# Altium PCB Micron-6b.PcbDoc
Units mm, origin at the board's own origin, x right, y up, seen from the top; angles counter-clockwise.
Board outline 45.08 x 23 mm, 2 copper layers (Top Layer, Bottom Layer), stack 1.021 mm thick; 39 components, 25 nets, 135 pads, 41 vias.
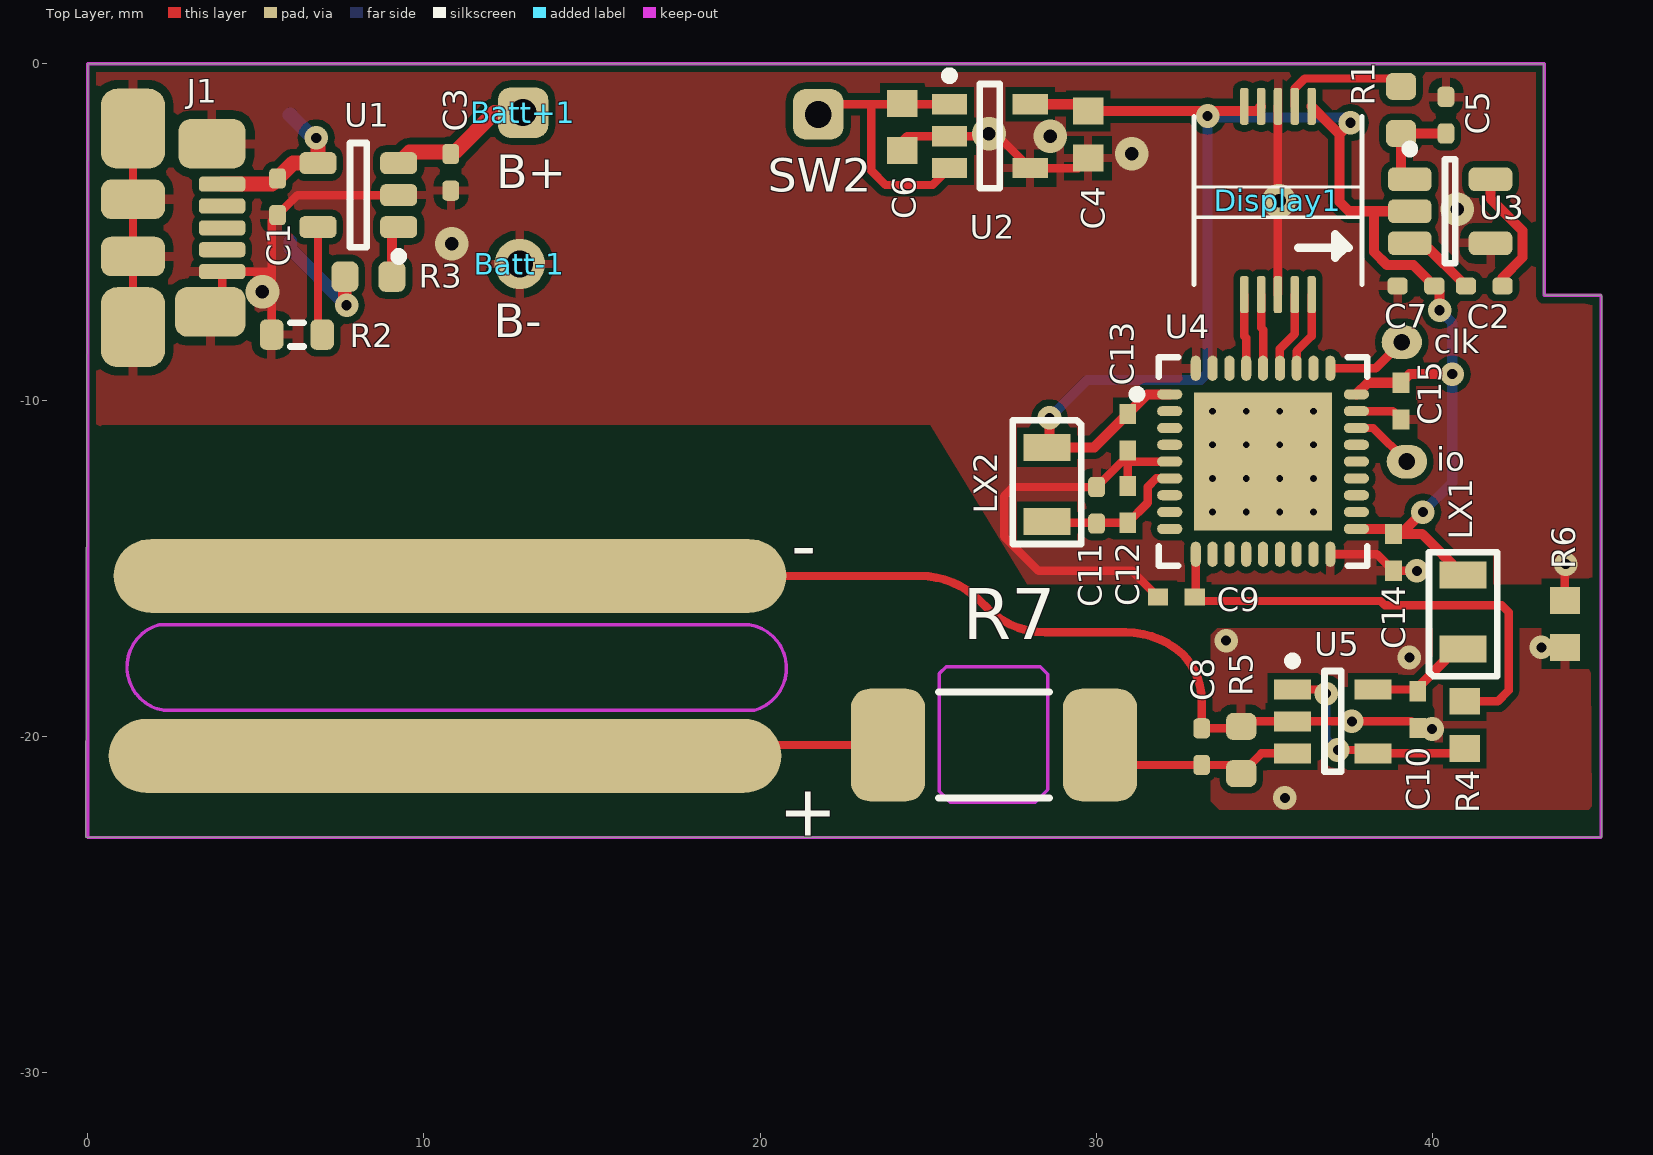
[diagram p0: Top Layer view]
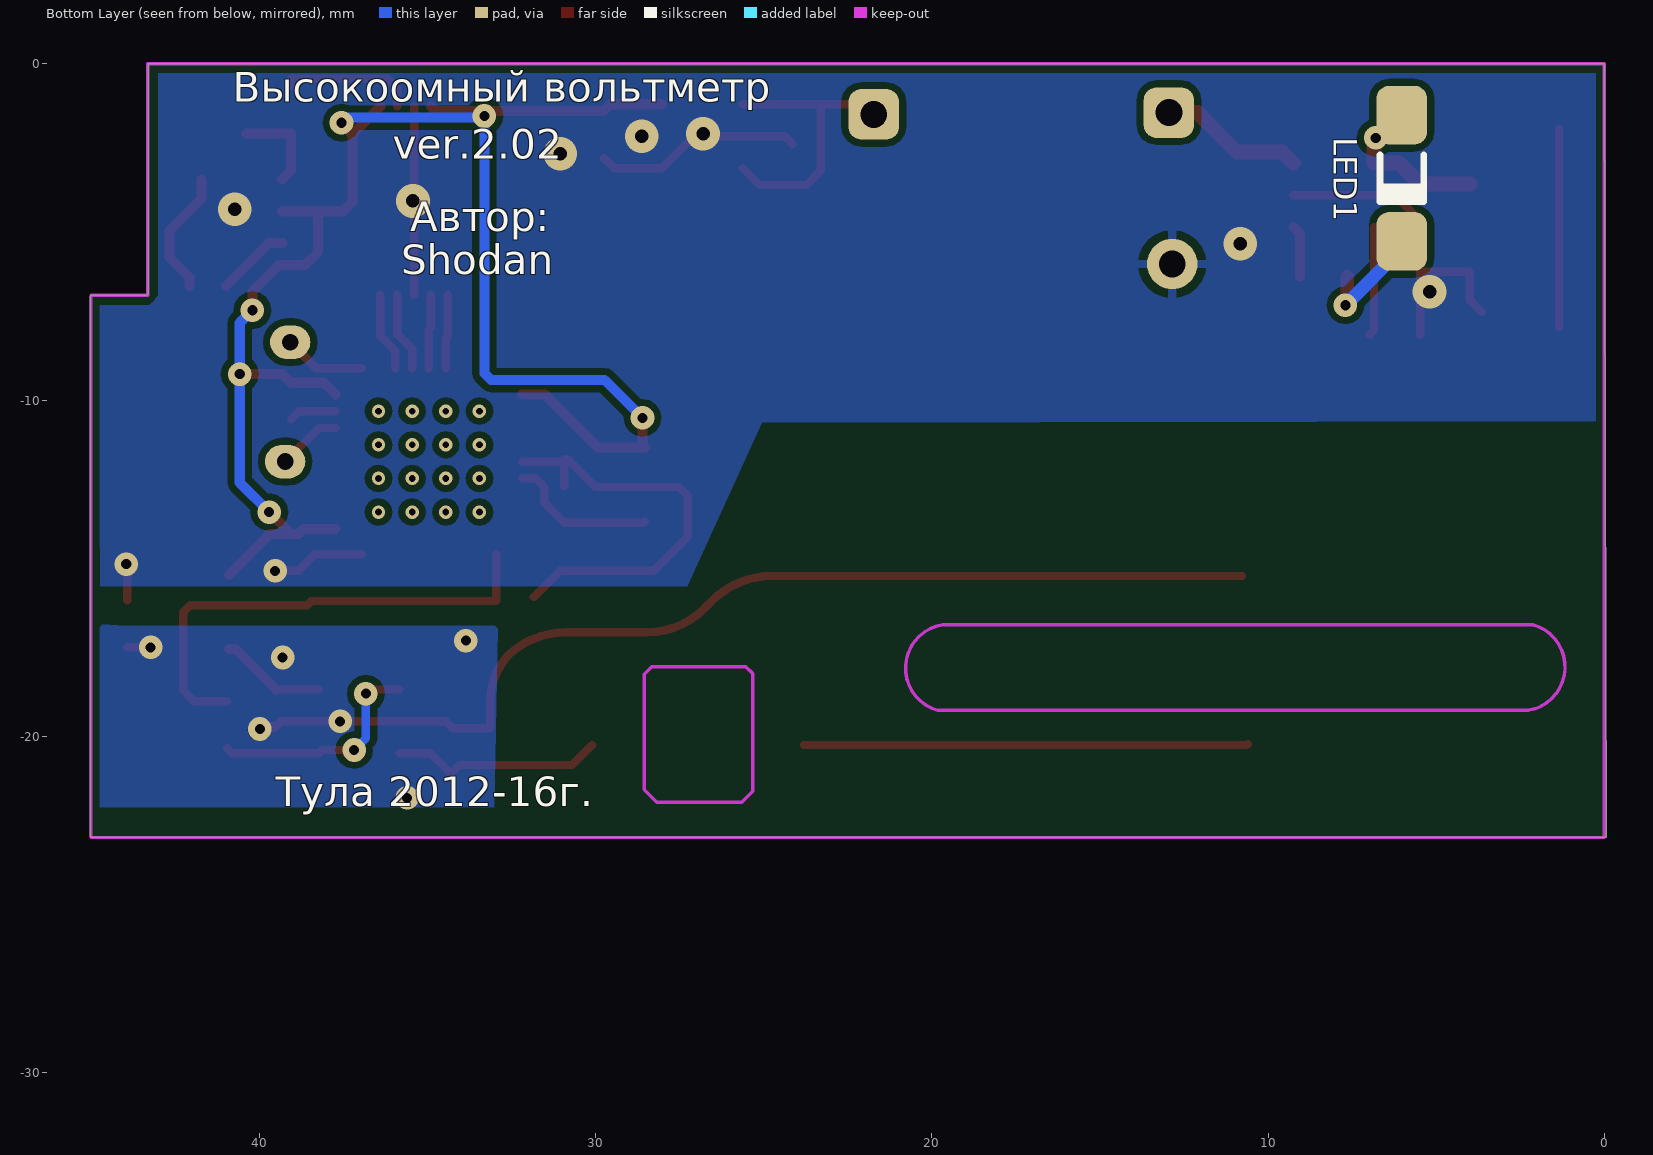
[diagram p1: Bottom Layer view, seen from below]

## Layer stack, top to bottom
Top Solder: solder mask 0.0102, Solder Resist, Dk 3.5
Top Layer: signal copper 0.0356
Dielectric1: dielectric 0.95, FR-4, Dk 4.8
Bottom Layer: signal copper 0.0356
Bottom Solder: solder mask 0.0102, Solder Resist, Dk 3.5

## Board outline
0,0 43.3,0 43.3,-6.85 43.325,-6.875 45,-6.875 45.025,-6.9 45.025,-23 0.1,-23 -0.05,-23

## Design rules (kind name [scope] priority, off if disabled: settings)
AssemblyTestPointUsage SilkToBoardRegionClearance_1 [All] p2:
Clearance Clearance_NetD2_1 [InNet('NetD2_1')] p1: gap=0.2
Clearance Clearance_NetC1_2 [InNet('NetC1_2')] p2: gap=0.2
Clearance Clearance_NetC1_1 [InNet('NetC1_1')] p3: gap=0.2
Clearance Clearance_400V [InNet('+400V')] p4: gap=0.8
Clearance Clearance_poly [InPolygon] p5: gap=0.2
Clearance [All] p6: gap=0.152
MatchedLengths DiffPair_DIFF100MatchedLengths [InDifferentialPairClass('DIFF100')] p1: tolerance=0.152 checknetsindiffpair=TRUE checkdiffpairvsdiffpair=FALSE checkxsignals=FALSE checkothers=FALSE
MinimumAnnularRing [All] p1: minimumring=0.152
MinimumSolderMaskSliver SilkscreenOverComponentPads_1 [All] p1: minsoldermaskwidth=0.254
MinimumSolderMaskSliver SilkToSolderMaskClearance [IsPad] p2: minsoldermaskwidth=0.254
MinimumSolderMaskSliver [All] p3: minsoldermaskwidth=0.254
MinimumSolderMaskSliver SilkscreenOverComponentPads_2 [All] p4: minsoldermaskwidth=0.254
PolygonConnect PolygonConnect_via [IsVia] p1: connectstyle=Direct reliefconductorwidth=0.254 reliefentries=4 polygonreliefangle="90 Angle" airgapwidth=0.254
PolygonConnect [All] p2: connectstyle=Relief reliefconductorwidth=0.254 reliefentries=4 polygonreliefangle="90 Angle" airgapwidth=0.254
RoutingVias [All] p1: holewidth=0.305 width=0.635 viastyle="Through Hole" minholewidth=0.305 minwidth=0.635 maxholewidth=0.711 maxwidth=1.27
ShortCircuit ShortCircuit_1 [All] p1: allowed=FALSE
ShortCircuit [All] p2: allowed=FALSE
SilkToBoardRegionClearance SilkToBoardRegionClearance_2 [All] p1:
SilkToBoardRegionClearance [All] p2:
SilkToSilkClearance [All] p1: silktosilkclearance=0.152
SilkToSolderMaskClearance SilkToSolderMaskClearance_1 [IsPad] p1: minsilkscreentomaskgap=0.254 clearancetoexposedcopper=TRUE
SilkToSolderMaskClearance SilkscreenOverComponentPads [IsPad] p2: minsilkscreentomaskgap=0.1 clearancetoexposedcopper=TRUE
SolderMaskExpansion [All] p1: expansion=0.102
Width [All] p1: maxlimit=2.54 minlimit=0.152 preferedwidth=0.254
25 further rules are at their usual default settings.

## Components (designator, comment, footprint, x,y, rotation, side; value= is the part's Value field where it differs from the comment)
+ "" "Sensor contact"#1 10.625,-20.575 r180 top (schematic designator HV+)
- "" "Sensor contact"#1 10.775,-15.225 r180 top (schematic designator HV-)
Batt+1 "" "SENSOR CONTACT"#1 12.575,-3.225 r90 top
Batt-1 "" "SENSOR CONTACT"#2 12.85,-5.95 r90 top
C1 "1uF" "0402 AVX"#1 5.65,-3.95 r180 top
C2 "1uF" "0402 AVX"#1 41.529,-6.604 r270 top
C3 "1uF" "0402 AVX"#1 10.8,-3.225 r180 top
C4 "1uF" 1608[0603]#1 29.75,-2.1 r90 top
C5 "1uF" "0402 AVX"#1 40.386,-1.524 r0 top
C6 "1uF" 1608[0603]#1 24.225,-1.875 r90 top
C7 "100nF" "0402 AVX"#1 39.497,-6.604 r90 top
C8 "100pF" "0402 AVX"#1 33.125,-20.3 r180 top
C9 "10nF" "0402 AVX"#2 32.375,-15.85 r270 top
C10 "100nF" "0402 AVX"#2 39.55,-19.2 r0 top
C11 "100nF" "0402 AVX"#1 30,-13.125 r180 top
C12 "100nF" "0402 AVX"#2 30.925,-13.1 r180 top
C13 "100nF" "0402 AVX"#2 30.925,-10.95 r0 top
C14 "100nF" "0402 AVX"#2 38.825,-14.525 r0 top
C15 "100nF" "0402 AVX"#2 39.05,-10.025 r0 top
clk "" "SENSOR CONTACT"#3 39.075,-8.275 r90 top
Display1 "Nokia 2760" DF23C-10DS-0.5V 32.893,-1.46 r90 top
io "" "SENSOR CONTACT"#3 39.225,-11.825 r90 top
J1 "Micro-USB" 47346-0001 4.75,-4.875 r270 top
LED1 "KPTD-3216SECK" KPTD-3216SECK 6.025,-3.4 r90 bottom
LX1 "Ferrite beard" Resistor 40.9,-16.3 r270 top
LX2 "Ferrite beard" Resistor 28.525,-12.5 r90 top
R1 "1R" 1608[0603]#2 39.052,-1.369 r270 top
R2 "10K" J1-0603 6.225,-8.05 r0 top
R3 "470R" 1608[0603]#2 8.35,-6.325 r180 top
R4 "10k" 1608[0603]#1 40.95,-19.65 r270 top
R5 "2.7M" 1608[0603]#2 34.3,-20.4 r90 top
R6 "0R" 1608[0603]#1 43.925,-16.65 r90 top
R7 "5G" HVF2512T5007FE 30.1,-21.925 r0 top
SW2 "" "Sensor contact"#2 21.725,-1.5 r90 top
U1 "MCP73831T-2ACI/OT" SOT-23-OT5_N 8.05,-3.9 r180 top
U2 "TPS78330DDCR" TI-DDC5_N 26.825,-2.15 r0 top
U3 "TPS60400DBV" SOT-23-OT5_M 40.513,-4.381 r0 top
U4 "STM32F103T8U6" VFQN36_V 34.95,-11.825 r0 top
U5 "AD8541ARTZ" ADI-RJ-5_N 37.025,-19.55 r0 top

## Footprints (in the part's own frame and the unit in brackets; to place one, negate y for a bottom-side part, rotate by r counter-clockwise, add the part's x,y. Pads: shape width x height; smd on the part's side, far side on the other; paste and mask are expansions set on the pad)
"0402 AVX"#1 [mm]
  rrect50% 0.5x0.6 smd: 1(0,0.545) 2(0,-0.545)
  body extent -0.25,-0.48 0.25,0.52, height 0.56
"0402 AVX"#2 [mm]
  rect 0.5x0.6 smd: 1(0,0.545) 2(0,-0.545)
  body extent -0.26,-0.5 0.26,0.5, height 0.36
1608[0603]#1 [mm] "Chip Capacitor, Body 1.6x0.8mm, IPC High Density"
  rect 0.8x0.9 smd: 1(-0.7,0) 2(0.7,0)
  body extent -0.87,-0.48 0.87,0.48, height 1.3
1608[0603]#2 [mm] "Chip Capacitor, Body 1.6x0.8mm, IPC High Density"
  rrect50% 0.8x0.9 smd: 1(-0.7,0) 2(0.7,0)
  body extent -0.87,-0.48 0.87,0.48, height 1.3
47346-0001 [mm] "Molex Mico-USB"
  rrect50% 0.45x1.38 smd: 1(-1.3,-0.75) 2(-0.65,-0.75) 3(0,-0.75) 4(0.65,-0.75) 5(1.3,-0.75)
  rrect50% 1.475x2 smd: MH1(-2.5,-1.05)
  rrect50% 1.475x2.1 smd: MH2(2.5,-1.1)
  rrect50% 2.375x1.9 smd: MH3(-2.95,-3.4) MH4(2.95,-3.4)
  rrect50% 1.175x1.9 smd: MH3(-0.85,-3.4) MH4(0.85,-3.4)
  body extent -3.95,-5.52 4.03,-0.09, height 2.77
ADI-RJ-5_N [mm] "SOT-23, 5-Leads, Body 2.9x1.6mm, Pitch 0.95mm, IPC Medium Density"
  rect 1.1x0.6 smd: 1(-1.2,0.95) 2(-1.2,0) 3(-1.2,-0.95) 4(1.2,-0.95) 5(1.2,0.95)
  silkscreen extent -1.32,-1.5 0.25,1.92, body extent -0.85,-1.5 0.85,1.5, height 1.45
DF23C-10DS-0.5V [mm]
  rrect50% 1.1x0.25 smd: 1(-5.4,-1.5) 2(-5.4,-2) 3(-5.4,-2.5) 4(-5.4,-3) 5(-5.4,-3.5) 6(0.2,-3.5) 7(0.2,-3) 8(0.2,-2.5) 9(0.2,-2) 10(0.2,-1.5)
  silkscreen extent -5.1,-5 -0.1,0, body extent -5.1,-5 -0.1,0, height 1.4
HVF2512T5007FE [mm] "Chip Resistor, 2-Leads, Body 7,31x3,20mm, IPC Low Density"
  rrect50% 2.2x3.35 smd: 1(-6.3,1.675) 2(0,1.675)
  silkscreen extent -4.8,0.1 -1.5,3.25, body extent -6.8,0.08 0.51,3.27, height 0.82
J1-0603 [mm] "Chip Resistor, Body 1.6x0.8mm, IPC High Density"
  rrect50% 0.7x0.9 smd: 1(-0.75,0) 2(0.75,0)
  silkscreen extent -0.2,-0.35 0.2,0.35, body extent -0.85,-0.48 0.85,0.48, height 0.9
KPTD-3216SECK [mm] "Chip Capacitor, 2-Leads, Body 3,2x1,6mm, IPC Medium Density"
  rrect50% 1.75x1.5 smd: 1(-1.875,0) 2(1.875,0)
  silkscreen extent -0.7,-0.65 0.7,0.65, body extent -1.6,-0.8 1.6,0.8, height 1.8
Resistor [mm]
  rect 0.8x1.4 smd: 1(-1.1,0) 2(1.1,0)
  silkscreen extent -1.78,-1.02 1.91,1.02, body extent -1.1,-0.7 1.2,0.7, height 1
"Sensor contact"#1 [mm]
  oval 20x2.2 smd: 1(0,0)
"Sensor contact"#2 [mm]
  rrect50% 1.5x1.5 hole 0.8: 1(0,0)
"SENSOR CONTACT"#1 [mm]
  rrect50% 1.5x1.5 hole 0.8: 1(1.775,-0.375)
"SENSOR CONTACT"#2 [mm]
  round 1.5 hole 0.8: 1(0,0)
"SENSOR CONTACT"#3 [mm]
  oval 1x1.2 hole 0.5: 1(0,0)
SOT-23-OT5_M [mm] "SOT23, 5-Leads, Body 2.9x1.6mm, Pitch 0.95mm, Lead Span 2.7mm, IPC Low Density"
  rrect50% 1.3x0.7 smd: 1(-1.2,0.95) 2(-1.2,0) 3(-1.2,-0.95) 4(1.2,-0.95) 5(1.2,0.95)
  silkscreen extent -1.32,-1.55 0.15,1.97, body extent -0.9,-1.55 0.9,1.55, height 1.45
SOT-23-OT5_N [mm] "SOT23, 5-Leads, Body 2.9x1.6mm, Pitch 0.95mm, Lead Span 2.7mm, IPC Medium Density"
  rrect50% 1.1x0.65 smd: 1(-1.2,0.95) 2(-1.2,0) 3(-1.2,-0.95) 4(1.2,-0.95) 5(1.2,0.95)
  silkscreen extent -1.33,-1.55 0.25,1.95, body extent -0.9,-1.55 0.9,1.55, height 1.45
TI-DDC5_N [mm] "SOT23, 5-Leads, Body 2.9x1.6mm, Pitch 0.95mm, IPC Medium Density"
  rect 1.05x0.6 smd: 1(-1.2,0.95) 2(-1.2,0) 3(-1.2,-0.95) 4(1.2,-0.95) 5(1.2,0.95)
  silkscreen extent -1.32,-1.55 0.3,1.92, body extent -0.87,-1.52 0.87,1.53, height 1.1
VFQN36_V [mm] "QFN, 36-Leads, Body 6x6mm, Pitch 0.5mm, ST Recommended"
  oval 0.75x0.3 smd: 1(-2.775,2) 2(-2.775,1.5) 3(-2.775,1) 4(-2.775,0.5) 5(-2.775,0) 6(-2.775,-0.5) 7(-2.775,-1) 8(-2.775,-1.5) 9(-2.775,-2) 19(2.775,-2) 20(2.775,-1.5) 21(2.775,-1) 22(2.775,-0.5) 23(2.775,0) 24(2.775,0.5) 25(2.775,1) 26(2.775,1.5) 27(2.775,2)
  oval 0.3x0.75 smd: 10(-2,-2.755) 11(-1.5,-2.755) 12(-1,-2.755) 13(-0.5,-2.755) 14(0,-2.755) 15(0.5,-2.755) 16(1,-2.755) 17(1.5,-2.755) 18(2,-2.755) 28(2,2.775) 29(1.5,2.775) 30(1,2.775) 31(0.5,2.775) 32(0,2.775) 33(-0.5,2.775) 34(-1,2.775) 35(-1.5,2.775) 36(-2,2.775)
  rect 4.1x4.1 smd: 37(0,0)
  silkscreen extent -3.87,-3.1 3.1,3.1, body extent -3.05,-3.05 3.05,3.05, height 1

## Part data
+ - Batt+1 Batt-1 clk io SW2: library part Plug, "Plug"
C1 C2 C3 C5 C7 C8 C9 C10 C11 C12 C13 C14 C15: library part "Cap Semi", "Capacitor (Semiconductor SIM Model)"
C4 C6: library part CAPACITOR, "Capacitor (Semiconductor SIM Model)"
J1: library part 0481900001, "USB On-The-Go (OTG) Mini-B Receptacle, Right Angle, SMT, 0.80mm (.031\") Pitch, Solder Tabs with Back Cover, Recessed Type"
LX1 LX2 R1 R3 R4 R5 R6 R7: library part "Resistor 0805"
R2: library part Res3, "Resistor"
U1: "Miniature Single-Cell, Fully Integrated Li-Ion, Li-Polymer Charge Management Controller, 4.2V, 5-Pin SOT-23, Industrial Temperature, Tape and Reel"
U2: "Single Output LDO, 150 mA, Fixed 3 V Output, 2.2 to 5.5 V Input, with Ultra-Low IQ, 5-pin SOT (DDC), -40 to 105 degC, Green (RoHS & no Sb/Br)"
U3: library part TPS60400
U4: "STM32 ARM-based 32-bit MCU with 64 Kbytes Flash, 36-pin VFQFPN, Industrial Temperature"
U5: library part AD8541ARTZ-R2, "Single Channel RRIO Operational Amplifier, 1 MHz BW, 920 mV/us SR, Industrial, 5-pin SOT23 (RJ-5), Reel"

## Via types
v1: diameter 0.7, hole 0.3, Top Layer to Bottom Layer, tented both sides, 18 vias
v2: diameter 0.4, hole 0.2, Top Layer to Bottom Layer, tented both sides, 16 vias
v3: diameter 1, hole 0.4, Top Layer to Bottom Layer, tented both sides, 7 vias

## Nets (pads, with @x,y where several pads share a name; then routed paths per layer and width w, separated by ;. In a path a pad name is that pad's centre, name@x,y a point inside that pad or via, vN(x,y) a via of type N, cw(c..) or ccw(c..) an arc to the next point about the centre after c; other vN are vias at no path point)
+3V: C4.2 C7.2 C13.1 C14.1 C15.1 Display1.6 Display1.9 Display1.10 LX1.1 LX2.2 U2.5 U3.2 U4.1 U4.19 U4.27 | length 54
  Top Layer w0.3: U2.5 29.55,-1.2 C4.2 v1@33.45,-1.4 ; v1(28.6,-10.525) 28.6,-11.325 LX2.2 29.93,-11.4 C13.1 31.505,-9.825 U4.1 ; v1(33.3,-1.55) v1@33.45,-1.4 ; Display1.9 34.754,-1.4 v1@33.45,-1.4 ; Display1.6 37.225,-2.093 ; v1(37.55,-1.75) 37.5,-1.8 37.5,-1.818 37.225,-2.093 ; U4.19 38.67,-13.825 C14.1 C14.1@39.045,-13.98 ; U4.27 38.07,-9.48 C15.1 39.305,-9.225 v1(40.575,-9.225) ; U3.2 38.25,-4.381 ; v1(39.7,-13.325) C14.1@39.045,-13.98 ; v1(40.2,-7.325) 40.2,-6.762 C7.2 39.422,-5.984 38.64,-5.984 38.25,-5.594 38.25,-4.381 ; LX1.1 39.68,-13.98 C14.1@39.045,-13.98 ; 37.225,-2.093 37.225,-4.1 37.507,-4.381 38.25,-4.381
  Bottom Layer w0.3: v1(28.6,-10.525) 29.725,-9.4 33.1,-9.4 33.3,-9.2 v1(33.3,-1.55) ; v1@33.437,-1.687 33.525,-1.6 37.55,-1.6 v1(37.55,-1.75) ; v1(39.7,-13.325) 40.575,-12.45 v1(40.575,-9.225) 40.575,-7.7 v1(40.2,-7.325)
-3V: Display1.7 R1.1 | length 4
  Top Layer w0.25: Display1.7 35.893,-0.73 36.19,-0.433 39.052,-0.433 R1.1
GND: Batt-1.1 C1.1 C3.1 C4.1 C5.1 C6.1 C7.1 C9.2 C11.2 C12.2 C13.2 C14.2 C15.2 Display1.3 Display1.8 J1.5 J1.MH1 J1.MH2 J1.MH3 J1.MH4 R2.1 R6.2 U1.2 U2.2 U2.4 U3.4 U4.5 U4.18 U4.26 U4.35 U4.36 | length 46.1
  Top Layer w0.25: J1.MH4@1.35,-7.825 1.35,-5.725 1.35,-4.025 J1.MH3@1.35,-1.925 ; J1.MH2 4,-7.025 J1.5 5.475,-6.175 ; R2.1 5.475,-6.175 ; U1.2 6.245,-3.9 C1.1 5.475,-4.67 5.475,-6.175 ; C6.1@24.125,-2.395 24.37,-2.15 U2.2 27.075,-2.15 U2.4 29.45,-3.1 C4.1 ; C12.2 C13.2@30.925,-11.75 ; C9.2 31.055,-15.075 28.275,-15.075 27.25,-14.05 27.25,-12.85 27.52,-12.58 C11.2 30.83,-11.75 C13.2@30.925,-11.75 ; U4.5 31,-11.825 C13.2@30.925,-11.75 ; Display1.3 Display1.8 ; U4.18 38.335,-14.58 C14.2 39.52,-15.07 v1(39.525,-15.075) ; U4.26 38.805,-10.325 C15.2 ; R6.2 43.925,-14.9 v1(43.95,-14.875)
  other v3: 5.2,-6.775 10.825,-5.35 40.725,-4.325 35.425,-4.075 31.05,-2.675 28.625,-2.15 26.8,-2.075
GND2: -.1 C8.2 C10.2 R5.2 R6.1 U5.2 | length 32.2
  Top Layer w0.25: -.1 24.743,-15.225 cw(c24.743,-17.765) 26.539,-15.969 26.764,-16.194 ccw(c28.469,-14.489) 28.469,-16.9 30.863,-16.9 cw(c30.863,-19.44) 32.544,-17.535 cw(c31.14,-18.939) 33.125,-18.939 C8.2 34.245,-19.755 R5.2 34.45,-19.55 U5.2 v1(37.59,-19.55) 39.355,-19.55 C10.2 C10.2@39.622,-19.673 ; v1(43.225,-17.35) R6.1
  Bottom Layer w0.25: v1(39.977,-19.776) v1@40,-19.799
  other v1: 35.6,-21.825 39.3,-17.65 33.85,-17.15
NetBatt+1_1: Batt+1.1 C3.2 U1.3 | length 4.3
  Top Layer w0.45: U1.3 9.575,-2.625 10.925,-2.625 12.1,-1.45 Batt+1.1
NetC1_2: C1.2 J1.1 LED1.2 U1.4 | length 5
  Top Layer w0.45: J1.1 5.48,-3.575 C1.2 6.105,-2.95 U1.4 6.85,-2.225 6.825,-2.2 v1(6.8,-2.2)
  Bottom Layer w0.45: LED1.2 6.725,-2.225 6.775,-2.225 v1(6.8,-2.2)
NetC2_1: C2.1 U3.5 | length 3.8
  Top Layer w0.3: U3.5 41.713,-4.006 42.665,-4.959 42.665,-5.76 42.074,-6.351 C2.1
NetC2_2: C2.2 U3.3 | length 2.2
  Top Layer w0.3: U3.3 39.711,-5.331 C2.2
NetC5_2: C5.2 R1.2 U3.1 | length 2.8
  Top Layer w0.3: U3.1 39.052,-3.171 R1.2 C5.2
NetC6_2: C6.2 SW2.1 U2.1 U2.3 | length 8.7
  Top Layer w0.25: SW2.1 22.025,-1.2 23.3,-1.2 ; U2.3 25.125,-3.6 23.725,-3.6 23.3,-3.175 23.3,-1.2 ; U2.1 23.3,-1.2
NetC8_1: C8.1 R5.1 R7.2 U5.3 | length 6.3
  Top Layer w0.25: R7.2 30.695,-20.845 C8.1 34.045,-20.845 R5.1 34.9,-20.5 U5.3
NetC9_1: C9.1 R4.1 U4.10 | length 14.6
  Top Layer w0.25: U4.10 32.95,-15.97 33.445,-15.97 38.445,-15.97 38.575,-16.1 42.05,-16.1 42.25,-16.3 42.25,-18.63 41.93,-18.95 R4.1
NetC10_1: C10.1 LX1.2 U5.5 | length 3.2
  Top Layer w0.25: U5.5 C10.1@39.495,-18.6
  Top Layer w0.3: C10.1@39.495,-18.6 40.695,-17.4 LX1.2
NetC11_1: C11.1 C12.1 LX2.1 U4.6 | length 4.5
  Top Layer w0.25: LX2.1 28.57,-13.645 C12.1 31.523,-13.047 31.523,-12.575 31.773,-12.325 U4.6
Netclk_1: clk.1 U4.28 | length 2.4
  Top Layer w0.25: U4.28 38.3,-9.05 clk.1
NetDisplay1_1: Display1.1 U4.33 | length 2.2
  Top Layer w0.25: Display1.1 34.393,-8.093 34.45,-8.15 U4.33
NetDisplay1_2: Display1.2 U4.32 | length 2.2
  Top Layer w0.25: Display1.2 34.893,-7.843 34.95,-7.9 U4.32
NetDisplay1_4: Display1.4 U4.31 | length 2.4
  Top Layer w0.25: U4.31 35.45,-8.47 35.893,-8.027 Display1.4
NetDisplay1_5: Display1.5 U4.30 | length 2.4
  Top Layer w0.25: U4.30 35.95,-8.539 36.393,-8.096 Display1.5
NetHV+_1: +.1 R7.1 | length 13.2
  Top Layer w0.25: +.1@10.6,-20.225 10.625,-20.25 R7.1
Netio_1: io.1 U4.25 | length 1.9
  Top Layer w0.25: U4.25 38.225,-10.825 io.1
NetLED1_1: LED1.1 R3.2 | length 3.5
  Top Layer w0.4: R3.2 7.65,-7.125 v1(7.7,-7.175)
  Bottom Layer w0.4: LED1.1 6.025,-5.5 v1(7.7,-7.175)
NetR2_2: R2.2 U1.5 | length 3.3
  Top Layer w0.25: U1.5 6.85,-7.925 R2.2
NetR3_1: R3.1 U1.1 | length 1.6
  Top Layer w0.3: R3.1 9.05,-5.05 U1.1
NetR4_2: R4.2 U5.1 U5.4 | length 6.8
  Top Layer w0.25: U5.1 36.7,-18.6 v1(36.825,-18.725) ; v1(37.175,-20.4) 38.125,-20.4 U5.4 40.8,-20.5 R4.2
  Bottom Layer w0.25: v1(36.825,-18.725) 36.825,-20.05 v1(37.175,-20.4)
pads on no net: J1.2 J1.3 J1.4 U4.2 U4.3 U4.4 U4.7 U4.8 U4.9 U4.11 U4.12 U4.13 U4.14 U4.15 U4.16 U4.17 U4.20 U4.21 U4.22 U4.23 U4.24 U4.29 U4.34 U4.37
copper on no net:
  other v2: 33.45,-13.325 34.45,-13.325 35.45,-13.325 36.45,-13.325 33.45,-12.325 34.45,-12.325 35.45,-12.325 36.45,-12.325 33.45,-11.325 34.45,-11.325 35.45,-11.325 36.45,-11.325 33.45,-10.325 34.45,-10.325 35.45,-10.325 36.45,-10.325

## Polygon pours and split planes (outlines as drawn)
GND2 on Top Layer "Bottom Layer-No Net" (solid, pour order 8): 44.675,-16.775 33.6,-16.775 33.4,-16.975 33.4,-21.925 33.65,-22.175 44.65,-22.175 44.725,-22.1
GND on Top Layer "Top Layer-No Net" (solid, pour order 9): 0,0 43.307,0 43.307,-6.875 44.75,-7.175 44.75,-22.725 21.9,-23 20.582,-22.725 0.225,-22.725
GND2 on Bottom Layer "Bottom Layer-No Net" (solid, pour order 4): 43.975,-16.7 32.9,-16.7 33.011,-22.1 44.9,-22.1 44.975,-22.025 44.975,-16.875 44.75,-16.65
GND on Bottom Layer "Bottom Layer-No Net" (solid, pour order 6): 44.725,-15.525 27.5,-15.525 27.275,-15.525 25.05,-10.675 0.3,-10.625 0.25,-10.675 0.25,-0.275 43,-0.275 43,-6.9 43.275,-7.175 44.75,-7.175 44.8,-7.125

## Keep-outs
Keep-Out Layer:
  lines w0.1: 0,-23 0,0 43.307,0 43.307,-6.875 45,-6.875 45,-23 21.9,-23 22.425,-23 11.475,-23 0,-23 ; 2.125,-16.675 ccw(c2.476,-17.933) 2.269,-19.222 19.825,-19.222 ccw(c19.474,-17.964) 19.681,-16.675 2.125,-16.675 ; 25.325,-21.625 25.325,-18.325 25.325,-18.125 25.525,-17.925 28.325,-17.925 28.55,-18.15 28.55,-21.575 28.175,-21.95 25.65,-21.95 25.325,-21.625

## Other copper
Top Layer:
  pour cut-out: 0.05,-22.9 21.9,-22.9 21.725,-21.6 28.463,-16.338 25.05,-10.725 0.43,-10.725 0.305,-10.85
  pour cut-out: 21.675,-15.467 44.042,-15.467 44.125,-16.675 33.362,-16.788 33.362,-22.2 44.875,-22.2 45.15,-22.85 45,-23 22,-23 21.7,-22.7

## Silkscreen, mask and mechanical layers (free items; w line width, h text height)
Top Overlay:
  text "B+" at 12.15,-3.7 h1
  text "B-" at 12.075,-8.125 h1
Bottom Overlay:
  text "Высокоомный вольтметр" at 40.784,-1.427 h1.5
  text "ver.2.02" at 36.029,-3.121 h1.5
  text "Автор:" at 35.5,-5.275 h1.5
  text "Shodan" at 35.775,-6.55 h1.5
  text "Тула 2012-16г." at 39.5,-22.375 h1.5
